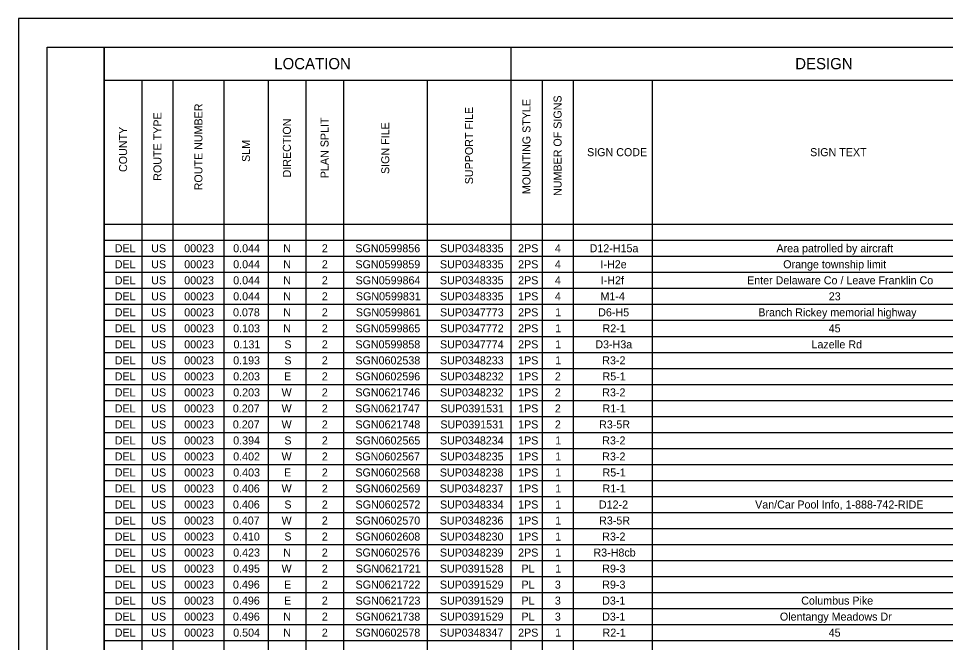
# Model space of a CAD drawing. Extents: x 0 to 34, y 0 to 22.
# Drawn here: x 0 to 16.22, y 11.09 to 22 of the extents above; entities that cross this region are included whole.
import ezdxf

# ---------------------------------------------------------------- set-up
doc = ezdxf.new("R2010")
doc.units = 0
for name, color, linetype in [('Default', 7, 'Continuous'), ('SH_Border', 7, 'Continuous'), ('SH_Cut_Line', 7, 'Continuous'), ('SH_Data', 7, 'Continuous')]:
    doc.layers.add(name, color=color, linetype=linetype)

msp = doc.modelspace()

# ---------------------------------------------------------------- linework, layer by layer
at = {"layer": 'SH_Border'}
for points in [[(0.5, 21.5), (1.5, 21.5), (1.5, 0.5), (0.5, 0.5)], [(1.5, 21.5), (33.5, 21.5), (33.5, 0.5), (1.5, 0.5)]]:
    msp.add_lwpolyline(points, close=True, dxfattribs=at)
at = {"layer": 'SH_Cut_Line'}
msp.add_lwpolyline([(0, 0), (34, 0), (34, 22), (0, 22)], close=True, dxfattribs=at)
at = {"layer": 'SH_Data'}
for p, q in [((1.5, 21.5), (32.004, 21.5)), ((8.615, 21.5), (8.615, 0.764)), ((1.5, 20.924), (28.232, 20.924)), ((1.5, 20.924), (1.5, 0.764)), ((2.159, 20.924), (2.159, 0.764)), ((2.702, 20.924), (2.702, 0.764)), ((3.592, 20.924), (3.592, 0.764)), ((4.366, 20.924), (4.366, 0.764)), ((5.025, 20.924), (5.025, 0.764)), ((5.684, 20.924), (5.684, 0.764)), ((7.149, 20.924), (7.149, 0.764)), ((9.159, 20.924), (9.159, 0.764)), ((9.702, 20.924), (9.702, 0.764)), ((11.086, 20.924), (11.086, 0.764)), ((1.5, 18.404), (32.004, 18.404)), ((1.5, 18.124), (32.004, 18.124)), ((1.5, 17.844), (32.004, 17.844)), ((1.5, 17.564), (32.004, 17.564)), ((1.5, 17.284), (32.004, 17.284)), ((1.5, 17.004), (32.004, 17.004)), ((1.5, 16.724), (32.004, 16.724)), ((1.5, 16.444), (32.004, 16.444)), ((1.5, 16.164), (32.004, 16.164)), ((1.5, 15.884), (32.004, 15.884)), ((1.5, 15.604), (32.004, 15.604)), ((1.5, 15.324), (32.004, 15.324)), ((1.5, 15.044), (32.004, 15.044)), ((1.5, 14.764), (32.004, 14.764)), ((1.5, 14.484), (32.004, 14.484)), ((1.5, 14.204), (32.004, 14.204)), ((1.5, 13.924), (32.004, 13.924)), ((1.5, 13.644), (32.004, 13.644)), ((1.5, 13.364), (32.004, 13.364)), ((1.5, 13.084), (32.004, 13.084)), ((1.5, 12.804), (32.004, 12.804)), ((1.5, 12.524), (32.004, 12.524)), ((1.5, 12.244), (32.004, 12.244)), ((1.5, 11.964), (32.004, 11.964)), ((1.5, 11.684), (32.004, 11.684)), ((1.5, 11.404), (32.004, 11.404)), ((1.5, 11.124), (32.004, 11.124))]:
    msp.add_line(p, q, dxfattribs=at)

# ---------------------------------------------------------------- texts
at = {"layer": 'Default'}
for s, height, p in [('LOCATION', 0.196, (4.474, 21.114)), ('DESIGN', 0.196, (13.589, 21.114)), ('SIGN CODE', 0.14, (9.948, 19.594)), ('SIGN TEXT', 0.14, (13.85, 19.594)), ('DEL', 0.14, (1.683, 17.914)), ('US', 0.14, (2.322, 17.914)), ('00023', 0.14, (2.899, 17.914)), ('0.044', 0.14, (3.756, 17.914)), ('N', 0.14, (4.632, 17.914)), ('2', 0.14, (5.307, 17.914)), ('SGN0599856', 0.14, (5.893, 17.914)), ('SUP0348335', 0.14, (7.373, 17.914)), ('2PS', 0.14, (8.741, 17.914)), ('4', 0.14, (9.384, 17.914)), ('D12-H15a', 0.14, (9.992, 17.914)), ('Area patrolled by aircraft', 0.14, (13.261, 17.914)), ('DEL', 0.14, (1.683, 17.634)), ('US', 0.14, (2.322, 17.634)), ('00023', 0.14, (2.899, 17.634)), ('0.044', 0.14, (3.756, 17.634)), ('N', 0.14, (4.632, 17.634)), ('2', 0.14, (5.307, 17.634)), ('SGN0599859', 0.14, (5.894, 17.634)), ('SUP0348335', 0.14, (7.373, 17.634)), ('2PS', 0.14, (8.741, 17.634)), ('4', 0.14, (9.384, 17.634)), ('I-H2e', 0.14, (10.182, 17.634)), ('Orange township limit', 0.14, (13.379, 17.634)), ('DEL', 0.14, (1.683, 17.354)), ('US', 0.14, (2.322, 17.354)), ('00023', 0.14, (2.899, 17.354)), ('0.044', 0.14, (3.756, 17.354)), ('N', 0.14, (4.632, 17.354)), ('2', 0.14, (5.307, 17.354)), ('SGN0599864', 0.14, (5.897, 17.354)), ('SUP0348335', 0.14, (7.373, 17.354)), ('2PS', 0.14, (8.741, 17.354)), ('4', 0.14, (9.384, 17.354)), ('I-H2f', 0.14, (10.187, 17.354)), ('Enter Delaware Co / Leave Franklin Co', 0.14, (12.747, 17.354)), ('DEL', 0.14, (1.683, 17.074)), ('US', 0.14, (2.322, 17.074)), ('00023', 0.14, (2.899, 17.074)), ('0.044', 0.14, (3.756, 17.074)), ('N', 0.14, (4.632, 17.074)), ('2', 0.14, (5.307, 17.074)), ('SGN0599831', 0.14, (5.902, 17.074)), ('SUP0348335', 0.14, (7.373, 17.074)), ('1PS', 0.14, (8.741, 17.074)), ('4', 0.14, (9.384, 17.074)), ('M1-4', 0.14, (10.182, 17.074)), ('23', 0.14, (14.176, 17.074)), ('DEL', 0.14, (1.683, 16.794)), ('US', 0.14, (2.322, 16.794)), ('00023', 0.14, (2.899, 16.794)), ('0.078', 0.14, (3.753, 16.794)), ('N', 0.14, (4.632, 16.794)), ('2', 0.14, (5.307, 16.794)), ('SGN0599861', 0.14, (5.902, 16.794)), ('SUP0347773', 0.14, (7.374, 16.794)), ('2PS', 0.14, (8.741, 16.794)), ('1', 0.14, (9.389, 16.794)), ('D6-H5', 0.14, (10.142, 16.794)), ('Branch Rickey memorial highway', 0.14, (12.944, 16.794)), ('DEL', 0.14, (1.683, 16.514)), ('US', 0.14, (2.322, 16.514)), ('00023', 0.14, (2.899, 16.514)), ('0.103', 0.14, (3.756, 16.514)), ('N', 0.14, (4.632, 16.514)), ('2', 0.14, (5.307, 16.514)), ('SGN0599865', 0.14, (5.895, 16.514)), ('SUP0347772', 0.14, (7.374, 16.514)), ('2PS', 0.14, (8.741, 16.514)), ('1', 0.14, (9.389, 16.514)), ('R2-1', 0.14, (10.218, 16.514)), ('45', 0.14, (14.175, 16.514)), ('Lazelle Rd', 0.14, (13.873, 16.234)), ('DEL', 0.14, (1.683, 16.234)), ('US', 0.14, (2.322, 16.234)), ('00023', 0.14, (2.899, 16.234)), ('0.131', 0.14, (3.762, 16.234)), ('S', 0.14, (4.651, 16.234)), ('2', 0.14, (5.307, 16.234)), ('SGN0599858', 0.14, (5.894, 16.234)), ('SUP0347774', 0.14, (7.374, 16.234)), ('2PS', 0.14, (8.741, 16.234)), ('1', 0.14, (9.389, 16.234)), ('D3-H3a', 0.14, (10.092, 16.234)), ('DEL', 0.14, (1.683, 15.954)), ('US', 0.14, (2.322, 15.954)), ('00023', 0.14, (2.899, 15.954)), ('0.193', 0.14, (3.756, 15.954)), ('S', 0.14, (4.651, 15.954)), ('2', 0.14, (5.307, 15.954)), ('SGN0602538', 0.14, (5.894, 15.954)), ('SUP0348233', 0.14, (7.374, 15.954)), ('1PS', 0.14, (8.741, 15.954)), ('1', 0.14, (9.389, 15.954)), ('R3-2', 0.14, (10.213, 15.954)), ('DEL', 0.14, (1.683, 15.674)), ('US', 0.14, (2.322, 15.674)), ('00023', 0.14, (2.899, 15.674)), ('0.203', 0.14, (3.756, 15.674)), ('E', 0.14, (4.645, 15.674)), ('2', 0.14, (5.307, 15.674)), ('SGN0602596', 0.14, (5.893, 15.674)), ('SUP0348232', 0.14, (7.374, 15.674)), ('1PS', 0.14, (8.741, 15.674)), ('2', 0.14, (9.384, 15.674)), ('R5-1', 0.14, (10.218, 15.674)), ('DEL', 0.14, (1.683, 15.394)), ('US', 0.14, (2.322, 15.394)), ('00023', 0.14, (2.899, 15.394)), ('0.203', 0.14, (3.756, 15.394)), ('W', 0.14, (4.602, 15.394)), ('2', 0.14, (5.307, 15.394)), ('SGN0621746', 0.14, (5.893, 15.394)), ('SUP0348232', 0.14, (7.374, 15.394)), ('1PS', 0.14, (8.741, 15.394)), ('2', 0.14, (9.384, 15.394)), ('R3-2', 0.14, (10.213, 15.394)), ('DEL', 0.14, (1.683, 15.114)), ('US', 0.14, (2.322, 15.114)), ('00023', 0.14, (2.899, 15.114)), ('0.207', 0.14, (3.75, 15.114)), ('W', 0.14, (4.602, 15.114)), ('2', 0.14, (5.307, 15.114)), ('SGN0621747', 0.14, (5.89, 15.114)), ('SUP0391531', 0.14, (7.38, 15.114)), ('1PS', 0.14, (8.741, 15.114)), ('2', 0.14, (9.384, 15.114)), ('R1-1', 0.14, (10.218, 15.114)), ('DEL', 0.14, (1.683, 14.834)), ('US', 0.14, (2.322, 14.834)), ('00023', 0.14, (2.899, 14.834)), ('0.207', 0.14, (3.75, 14.834)), ('W', 0.14, (4.602, 14.834)), ('2', 0.14, (5.307, 14.834)), ('SGN0621748', 0.14, (5.894, 14.834)), ('SUP0391531', 0.14, (7.38, 14.834)), ('1PS', 0.14, (8.741, 14.834)), ('2', 0.14, (9.384, 14.834)), ('R3-5R', 0.14, (10.158, 14.834)), ('DEL', 0.14, (1.683, 14.554)), ('US', 0.14, (2.322, 14.554)), ('00023', 0.14, (2.899, 14.554)), ('0.394', 0.14, (3.756, 14.554)), ('S', 0.14, (4.651, 14.554)), ('2', 0.14, (5.307, 14.554)), ('SGN0602565', 0.14, (5.895, 14.554)), ('SUP0348234', 0.14, (7.374, 14.554)), ('1PS', 0.14, (8.741, 14.554)), ('1', 0.14, (9.389, 14.554)), ('R3-2', 0.14, (10.213, 14.554)), ('DEL', 0.14, (1.683, 14.274)), ('US', 0.14, (2.322, 14.274)), ('00023', 0.14, (2.899, 14.274)), ('0.402', 0.14, (3.756, 14.274)), ('W', 0.14, (4.602, 14.274)), ('2', 0.14, (5.307, 14.274)), ('SGN0602567', 0.14, (5.89, 14.274)), ('SUP0348235', 0.14, (7.373, 14.274)), ('1PS', 0.14, (8.741, 14.274)), ('1', 0.14, (9.389, 14.274)), ('R3-2', 0.14, (10.213, 14.274)), ('DEL', 0.14, (1.683, 13.994)), ('US', 0.14, (2.322, 13.994)), ('00023', 0.14, (2.899, 13.994)), ('0.403', 0.14, (3.756, 13.994)), ('E', 0.14, (4.645, 13.994)), ('2', 0.14, (5.307, 13.994)), ('SGN0602568', 0.14, (5.894, 13.994)), ('SUP0348238', 0.14, (7.371, 13.994)), ('1PS', 0.14, (8.741, 13.994)), ('1', 0.14, (9.389, 13.994)), ('R5-1', 0.14, (10.218, 13.994)), ('DEL', 0.14, (1.683, 13.714)), ('US', 0.14, (2.322, 13.714)), ('00023', 0.14, (2.899, 13.714)), ('0.406', 0.14, (3.752, 13.714)), ('W', 0.14, (4.602, 13.714)), ('2', 0.14, (5.307, 13.714)), ('SGN0602569', 0.14, (5.894, 13.714)), ('SUP0348237', 0.14, (7.368, 13.714)), ('1PS', 0.14, (8.741, 13.714)), ('1', 0.14, (9.389, 13.714)), ('R1-1', 0.14, (10.218, 13.714)), ('DEL', 0.14, (1.683, 13.434)), ('US', 0.14, (2.322, 13.434)), ('00023', 0.14, (2.899, 13.434)), ('0.406', 0.14, (3.752, 13.434)), ('S', 0.14, (4.651, 13.434)), ('2', 0.14, (5.307, 13.434)), ('SGN0602572', 0.14, (5.896, 13.434)), ('SUP0348334', 0.14, (7.374, 13.434)), ('1PS', 0.14, (8.741, 13.434)), ('1', 0.14, (9.389, 13.434)), ('D12-2', 0.14, (10.155, 13.434)), ('Van/Car Pool Info, 1-888-742-RIDE', 0.14, (12.888, 13.434)), ('DEL', 0.14, (1.683, 13.154)), ('US', 0.14, (2.322, 13.154)), ('00023', 0.14, (2.899, 13.154)), ('0.407', 0.14, (3.75, 13.154)), ('W', 0.14, (4.602, 13.154)), ('2', 0.14, (5.307, 13.154)), ('SGN0602570', 0.14, (5.893, 13.154)), ('SUP0348236', 0.14, (7.37, 13.154)), ('1PS', 0.14, (8.741, 13.154)), ('1', 0.14, (9.389, 13.154)), ('R3-5R', 0.14, (10.158, 13.154)), ('DEL', 0.14, (1.683, 12.874)), ('US', 0.14, (2.322, 12.874)), ('00023', 0.14, (2.899, 12.874)), ('0.410', 0.14, (3.753, 12.874)), ('S', 0.14, (4.651, 12.874)), ('2', 0.14, (5.307, 12.874)), ('SGN0602608', 0.14, (5.894, 12.874)), ('SUP0348230', 0.14, (7.371, 12.874)), ('1PS', 0.14, (8.741, 12.874)), ('1', 0.14, (9.389, 12.874)), ('R3-2', 0.14, (10.213, 12.874)), ('DEL', 0.14, (1.683, 12.594)), ('US', 0.14, (2.322, 12.594)), ('00023', 0.14, (2.899, 12.594)), ('0.423', 0.14, (3.756, 12.594)), ('N', 0.14, (4.632, 12.594)), ('2', 0.14, (5.307, 12.594)), ('SGN0602576', 0.14, (5.893, 12.594)), ('SUP0348239', 0.14, (7.372, 12.594)), ('2PS', 0.14, (8.741, 12.594)), ('1', 0.14, (9.389, 12.594)), ('R3-H8cb', 0.14, (10.059, 12.594)), ('DEL', 0.14, (1.683, 12.314)), ('US', 0.14, (2.322, 12.314)), ('00023', 0.14, (2.899, 12.314)), ('0.495', 0.14, (3.755, 12.314)), ('W', 0.14, (4.602, 12.314)), ('2', 0.14, (5.307, 12.314)), ('SGN0621721', 0.14, (5.902, 12.314)), ('SUP0391528', 0.14, (7.371, 12.314)), ('PL', 0.14, (8.799, 12.314)), ('1', 0.14, (9.389, 12.314)), ('R9-3', 0.14, (10.213, 12.314)), ('DEL', 0.14, (1.683, 12.034)), ('US', 0.14, (2.322, 12.034)), ('00023', 0.14, (2.899, 12.034)), ('0.496', 0.14, (3.752, 12.034)), ('E', 0.14, (4.645, 12.034)), ('2', 0.14, (5.307, 12.034)), ('SGN0621722', 0.14, (5.896, 12.034)), ('SUP0391529', 0.14, (7.372, 12.034)), ('PL', 0.14, (8.799, 12.034)), ('3', 0.14, (9.384, 12.034)), ('R9-3', 0.14, (10.213, 12.034)), ('DEL', 0.14, (1.683, 11.754)), ('US', 0.14, (2.322, 11.754)), ('00023', 0.14, (2.899, 11.754)), ('0.496', 0.14, (3.752, 11.754)), ('E', 0.14, (4.645, 11.754)), ('2', 0.14, (5.307, 11.754)), ('SGN0621723', 0.14, (5.897, 11.754)), ('SUP0391529', 0.14, (7.372, 11.754)), ('PL', 0.14, (8.799, 11.754)), ('3', 0.14, (9.384, 11.754)), ('D3-1', 0.14, (10.211, 11.754)), ('Columbus Pike', 0.14, (13.694, 11.754)), ('DEL', 0.14, (1.683, 11.474)), ('US', 0.14, (2.322, 11.474)), ('00023', 0.14, (2.899, 11.474)), ('0.496', 0.14, (3.752, 11.474)), ('N', 0.14, (4.632, 11.474)), ('2', 0.14, (5.307, 11.474)), ('SGN0621738', 0.14, (5.894, 11.474)), ('SUP0391529', 0.14, (7.372, 11.474)), ('PL', 0.14, (8.799, 11.474)), ('3', 0.14, (9.384, 11.474)), ('D3-1', 0.14, (10.211, 11.474)), ('Olentangy Meadows Dr', 0.14, (13.321, 11.474)), ('DEL', 0.14, (1.683, 11.194)), ('US', 0.14, (2.322, 11.194)), ('00023', 0.14, (2.899, 11.194)), ('0.504', 0.14, (3.756, 11.194)), ('N', 0.14, (4.632, 11.194)), ('2', 0.14, (5.307, 11.194)), ('SGN0602578', 0.14, (5.894, 11.194)), ('SUP0348347', 0.14, (7.368, 11.194)), ('2PS', 0.14, (8.741, 11.194)), ('1', 0.14, (9.389, 11.194)), ('R2-1', 0.14, (10.218, 11.194)), ('45', 0.14, (14.175, 11.194))]:
    msp.add_text(s, height=height, dxfattribs=at).set_placement(p)
for s, p in [('NUMBER OF SIGNS', (9.501, 18.898)), ('ROUTE NUMBER', (3.217, 18.996)), ('SUPPORT FILE', (7.952, 19.103)), ('MOUNTING STYLE', (8.957, 18.93)), ('ROUTE TYPE', (2.501, 19.164)), ('DIRECTION', (4.765, 19.222)), ('PLAN SPLIT', (5.424, 19.209)), ('SIGN FILE', (6.486, 19.282)), ('COUNTY', (1.899, 19.317)), ('SLM', (4.049, 19.493))]:
    msp.add_text(s, height=0.14, rotation=90, dxfattribs=at).set_placement(p)

doc.saveas('drawing.dxf')
